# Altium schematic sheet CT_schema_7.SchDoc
size 254 x 194 mm
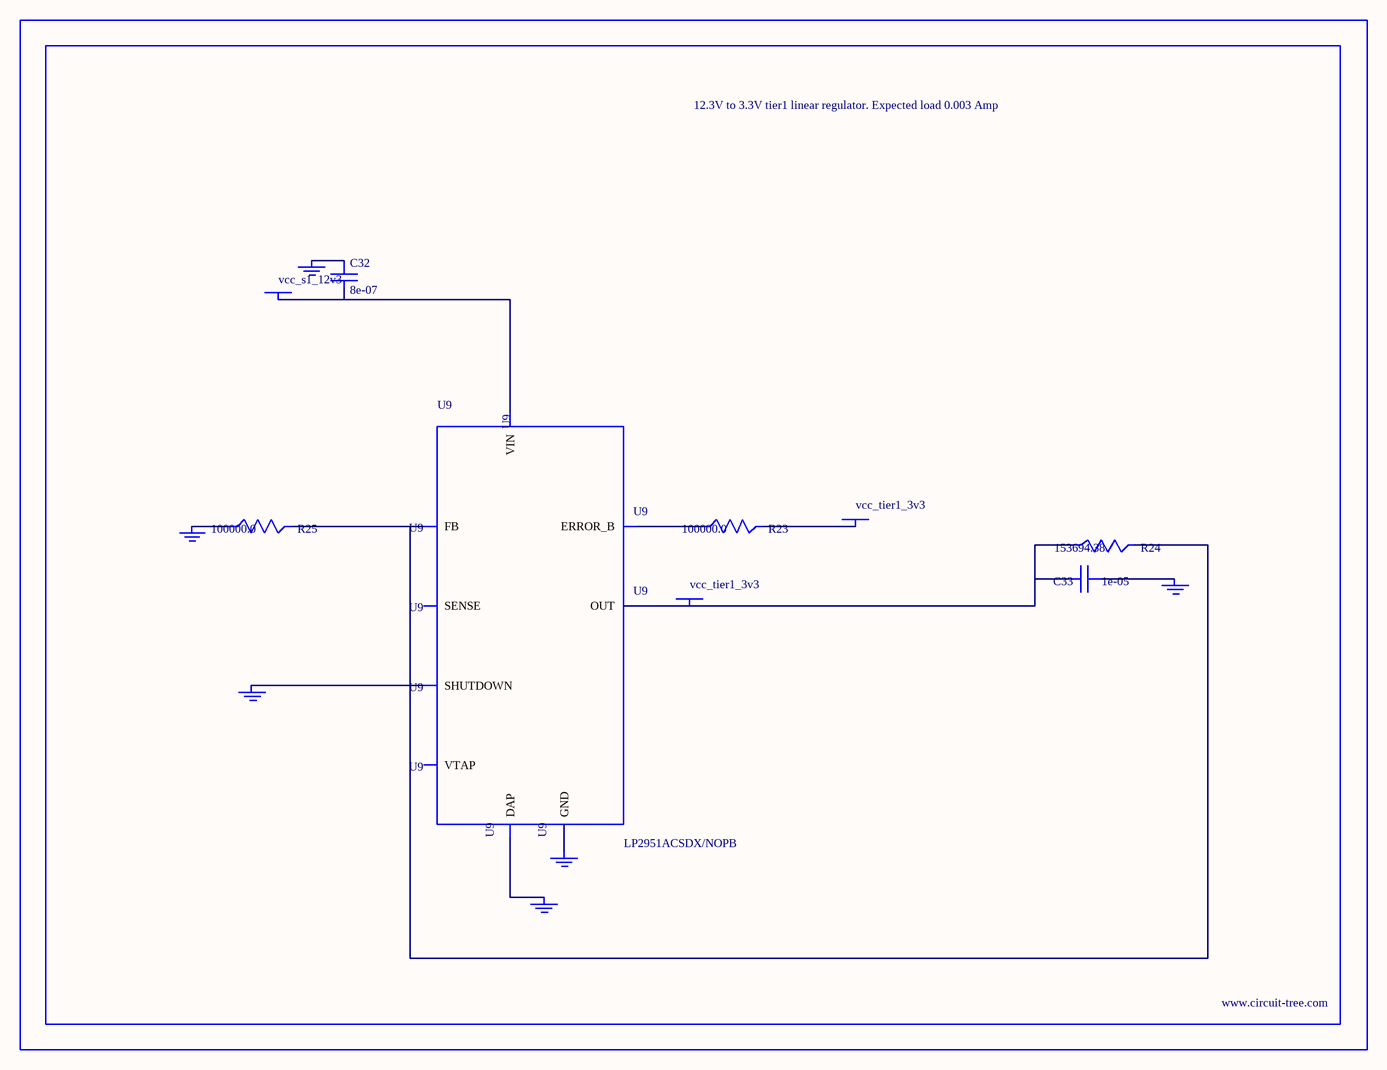
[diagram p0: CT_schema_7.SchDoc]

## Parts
BORDER6  (no value)
C32  8e-07  [R0603]
C33  1e-05  [C1210]
GND_INSTANCE_6_0  (no value)
GND_INSTANCE_6_1  (no value)
GND_INSTANCE_6_2  (no value)
GND_INSTANCE_6_3  (no value)
GND_INSTANCE_6_4  (no value)
GND_INSTANCE_6_5  (no value)
POWER_INSTANCE_6_0  vcc_tier1_3v3
POWER_INSTANCE_6_1  vcc_s1_12v3
POWER_INSTANCE_6_2  vcc_tier1_3v3
R23  100000.0  [R0603]
R24  153694.38  [R0603]
R25  100000.0  [R0603]
U9  LP2951ACSDX/NOPB  [WSON-8]

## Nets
NetC32_1: C32.1 GND_INSTANCE_6_3.0(GND)
NetC32_2: C32.2 POWER_INSTANCE_6_1.0(PWR) U9.8(VIN)
NetC33_1: C33.1 GND_INSTANCE_6_0.0(GND)
NetC33_2: C33.2 POWER_INSTANCE_6_2.0(PWR) R24.1 U9.1(OUT)
NetGND_INSTANCE_6_1_0: GND_INSTANCE_6_1.0(GND) U9.3(SHUTDOWN)
NetGND_INSTANCE_6_2_0: GND_INSTANCE_6_2.0(GND) R25.1
NetGND_INSTANCE_6_4_0: GND_INSTANCE_6_4.0(GND) U9.PAD(DAP)
NetGND_INSTANCE_6_5_0: GND_INSTANCE_6_5.0(GND) U9.4(GND)
NetPOWER_INSTANCE_6_0_0: POWER_INSTANCE_6_0.0(PWR) R23.2
NetR23_1: R23.1 U9.5(ERROR_B)
NetR24_2: R24.2 R25.2 U9.7(FB)

Not connected (* = marked no-connect by the designer): U9 2(SENSE) 6(VTAP)

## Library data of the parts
BORDER6 = BORDER_PAGE6
C32 = C32
C33 = GRM32DR61E106MA12L
GND_INSTANCE_6_0-GND_INSTANCE_6_5 = GND
POWER_INSTANCE_6_0-POWER_INSTANCE_6_2 = PWR
R23 R25 = RC0603JR-07100KL
R24 = R24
